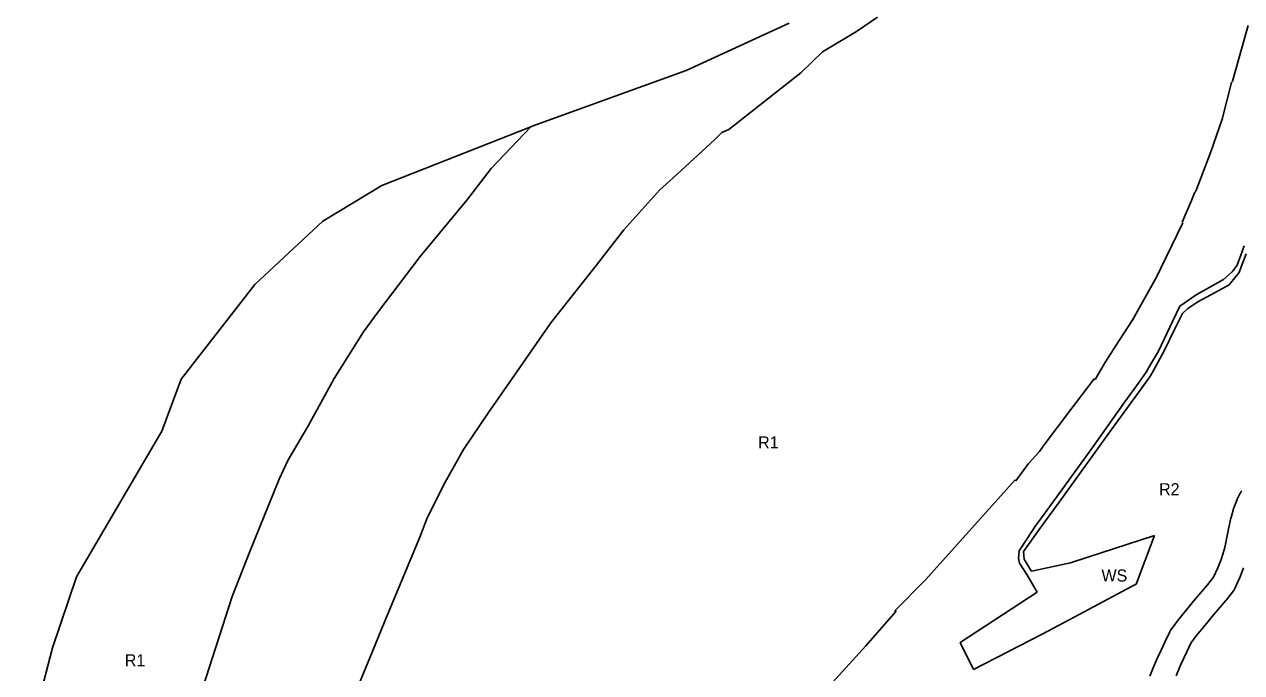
# Model space of a CAD drawing. Extents: x 7413438 to 7416393, y 5541665 to 5544118.
# Drawn here: x 7413443 to 7414051, y 5542525 to 5542849 of the extents above; entities that cross this region are included whole.
import ezdxf

# ---------------------------------------------------------------- set-up
doc = ezdxf.new("R2010")
doc.units = 0
doc.layers.add('linie_rozgraniczajace', color=7, linetype='Continuous')
doc.layers.add('oznaczenia_przeznaczen', color=7, linetype='Continuous')

msp = doc.modelspace()

# ---------------------------------------------------------------- linework, layer by layer
at = {"layer": 'linie_rozgraniczajace'}
for p, q in [((7413869.45, 5542852.48), (7413858.94, 5542845.23)), ((7413773.76, 5542825.75), (7413825.22, 5542849.45)), ((7413858.94, 5542845.23), (7413841.9, 5542835.15)), ((7414054.61, 5542848.19), (7414046.86, 5542820.34)), ((7413841.9, 5542835.15), (7413831.13, 5542824.66)), ((7413696.93, 5542797.92), (7413773.76, 5542825.75)), ((7413831.13, 5542824.66), (7413795.08, 5542796.31)), ((7414046.84, 5542820.33), (7414046.23, 5542819.81)), ((7414046.86, 5542820.34), (7414046.84, 5542820.33)), ((7414046.23, 5542819.81), (7414041.67, 5542801.46)), ((7413621.76, 5542768.27), (7413696.25, 5542797.65)), ((7413696.25, 5542797.65), (7413676.41, 5542776.84)), ((7413696.25, 5542797.65), (7413696.93, 5542797.92)), ((7413795.08, 5542796.31), (7413791.56, 5542794.75)), ((7414041.67, 5542801.46), (7414035.98, 5542785.07)), ((7413787.92, 5542791.04), (7413767.26, 5542772.18)), ((7413791.56, 5542794.75), (7413787.92, 5542791.04)), ((7414035.98, 5542785.07), (7414028.55, 5542765.43)), ((7413676.41, 5542776.84), (7413664.16, 5542760.89)), ((7413767.26, 5542772.18), (7413760.68, 5542766.04)), ((7413592.26, 5542750.42), (7413621.76, 5542768.27)), ((7413760.68, 5542766.04), (7413742.71, 5542746.15)), ((7414028.55, 5542765.43), (7414027.98, 5542764.93)), ((7413664.16, 5542760.89), (7413640.83, 5542732.82)), ((7414026.38, 5542760.85), (7414021.74, 5542749.9)), ((7414027.98, 5542764.93), (7414026.38, 5542760.85)), ((7413558.2, 5542718.88), (7413592.26, 5542750.42)), ((7414021.94, 5542749.71), (7414008.22, 5542721.17)), ((7414021.74, 5542749.9), (7414021.94, 5542749.71)), ((7413742.71, 5542746.15), (7413728.83, 5542728.33)), ((7414052.57, 5542738.17), (7414050.9, 5542733.49)), ((7413640.83, 5542732.82), (7413619.95, 5542705.13)), ((7414050.9, 5542733.49), (7414049.12, 5542728.52)), ((7414051.17, 5542727.63), (7414053.69, 5542734.12)), ((7413728.83, 5542728.33), (7413722.52, 5542720.3)), ((7414046.59, 5542725.22), (7414042.24, 5542721.37)), ((7414045.14, 5542718.61), (7414050.21, 5542724.83)), ((7414049.12, 5542728.52), (7414046.59, 5542725.22)), ((7414050.21, 5542724.83), (7414051.17, 5542727.63)), ((7413521.45, 5542671.43), (7413558.2, 5542718.88)), ((7413722.52, 5542720.3), (7413706.1, 5542699.62)), ((7414008.13, 5542721.26), (7413996.99, 5542701.33)), ((7414008.22, 5542721.17), (7414008.13, 5542721.26)), ((7414042.24, 5542721.37), (7414028.59, 5542713.58)), ((7414038.12, 5542714.82), (7414045.14, 5542718.61)), ((7414028.59, 5542713.58), (7414020.51, 5542707.94)), ((7414029.45, 5542710.14), (7414038.12, 5542714.82)), ((7413619.95, 5542705.13), (7413612.58, 5542695.16)), ((7414020.51, 5542707.94), (7414016.76, 5542700.29)), ((7414021.75, 5542704.28), (7414024.53, 5542706.88)), ((7414024.53, 5542706.88), (7414029.45, 5542710.14)), ((7413706.1, 5542699.62), (7413689.26, 5542675.23)), ((7413996.98, 5542701.34), (7413990.2, 5542690.75)), ((7413996.99, 5542701.33), (7413996.98, 5542701.34)), ((7414016.76, 5542700.29), (7414009.79, 5542685.54)), ((7414017.87, 5542696.28), (7414021.75, 5542704.28)), ((7413612.58, 5542695.16), (7413597.98, 5542671.81)), ((7414012.71, 5542685.63), (7414017.87, 5542696.28)), ((7413990.15, 5542690.76), (7413983.36, 5542680.23)), ((7413990.2, 5542690.75), (7413990.15, 5542690.76)), ((7413983.35, 5542680.23), (7413978.18, 5542671.36)), ((7413983.36, 5542680.23), (7413983.35, 5542680.23)), ((7414009.79, 5542685.54), (7414006.39, 5542679.6)), ((7414007.3, 5542675.86), (7414011.52, 5542683.49)), ((7414011.52, 5542683.49), (7414012.71, 5542685.63)), ((7413689.26, 5542675.23), (7413675.1, 5542654.93)), ((7414003.59, 5542675.01), (7414000.09, 5542670.09)), ((7414006.39, 5542679.6), (7414003.59, 5542675.01)), ((7414005.86, 5542673.25), (7414007.3, 5542675.86)), ((7413511.75, 5542645.52), (7413521.45, 5542671.43)), ((7413597.98, 5542671.81), (7413584.73, 5542647.85)), ((7413977.62, 5542671.62), (7413966.51, 5542657.01)), ((7413978.1, 5542671.39), (7413977.62, 5542671.62)), ((7413978.18, 5542671.36), (7413978.1, 5542671.39)), ((7414000.09, 5542670.09), (7413993.07, 5542660.22)), ((7413996.74, 5542660.53), (7414002.54, 5542668.48)), ((7414002.54, 5542668.48), (7414005.86, 5542673.25)), ((7413966.51, 5542657.01), (7413952.69, 5542638.7)), ((7413993.07, 5542660.22), (7413975.12, 5542635)), ((7413985.04, 5542644.49), (7413996.74, 5542660.53)), ((7413675.1, 5542654.93), (7413662.58, 5542636.31)), ((7413469.16, 5542572.7), (7413511.75, 5542645.52)), ((7413584.73, 5542647.85), (7413574.79, 5542630.94)), ((7413977.31, 5542633.81), (7413985.04, 5542644.49)), ((7413952.69, 5542638.7), (7413950.29, 5542635.4)), ((7413662.58, 5542636.31), (7413653.2, 5542619.62)), ((7413950.53, 5542635.53), (7413944.86, 5542629.38)), ((7413950.29, 5542635.4), (7413950.53, 5542635.53)), ((7413975.12, 5542635), (7413958.9, 5542612.62)), ((7413960.16, 5542610.09), (7413977.31, 5542633.81)), ((7413574.79, 5542630.94), (7413570.43, 5542621.47)), ((7413944.86, 5542629.38), (7413938.55, 5542620.67)), ((7413570.43, 5542621.47), (7413555.78, 5542585.31)), ((7413653.2, 5542619.62), (7413644.6, 5542602.58)), ((7413938.18, 5542621.18), (7413893.47, 5542571.16)), ((7413938.35, 5542620.94), (7413938.18, 5542621.18)), ((7413938.55, 5542620.67), (7413938.35, 5542620.94)), ((7414050.67, 5542614.52), (7414049.32, 5542611.82)), ((7414050.73, 5542614.63), (7414050.67, 5542614.52)), ((7414050.92, 5542614.98), (7414050.73, 5542614.63)), ((7414051.14, 5542615.3), (7414050.92, 5542614.98)), ((7414051.37, 5542615.62), (7414051.14, 5542615.3)), ((7414051.5, 5542615.77), (7414051.37, 5542615.62)), ((7413950.12, 5542596.36), (7413960.16, 5542610.09)), ((7413958.9, 5542612.62), (7413951.37, 5542602.21)), ((7414047.54, 5542607.27), (7414047.51, 5542607.18)), ((7414049.1, 5542611.31), (7414047.54, 5542607.27)), ((7414049.21, 5542611.58), (7414049.1, 5542611.31)), ((7414049.32, 5542611.82), (7414049.21, 5542611.58)), ((7413644.6, 5542602.58), (7413640.64, 5542592.55)), ((7413951.37, 5542602.21), (7413948.44, 5542598.18)), ((7414046.02, 5542602.04), (7414044.78, 5542596.7)), ((7414046.1, 5542602.35), (7414046.02, 5542602.04)), ((7414047.37, 5542606.77), (7414046.1, 5542602.35)), ((7414047.38, 5542606.81), (7414047.37, 5542606.77)), ((7414047.51, 5542607.18), (7414047.38, 5542606.81)), ((7413942.37, 5542585.38), (7413950.12, 5542596.36)), ((7413948.44, 5542598.18), (7413944.35, 5542591.98)), ((7414044.74, 5542596.51), (7414042.92, 5542587.35)), ((7414044.77, 5542596.66), (7414044.74, 5542596.51)), ((7414044.78, 5542596.7), (7414044.77, 5542596.66)), ((7413640.64, 5542592.55), (7413624.4, 5542553.49)), ((7413944.35, 5542591.98), (7413940.24, 5542585.74)), ((7414007.85, 5542593.32), (7413974.54, 5542582.57)), ((7413998.73, 5542569.12), (7414007.85, 5542593.32)), ((7413555.78, 5542585.31), (7413547.01, 5542562.96)), ((7413940.24, 5542585.74), (7413939.9, 5542581.99)), ((7413942.68, 5542581.49), (7413942.37, 5542585.38)), ((7414041.97, 5542584.06), (7414041.1, 5542581.34)), ((7414042.92, 5542587.35), (7414041.97, 5542584.06)), ((7413939.9, 5542581.99), (7413940.31, 5542579.55)), ((7413940.31, 5542579.55), (7413944.06, 5542573.97)), ((7413946.23, 5542575.65), (7413942.68, 5542581.49)), ((7413965.91, 5542579.78), (7413947.23, 5542575.74)), ((7413974.54, 5542582.57), (7413965.91, 5542579.78)), ((7414039.56, 5542577.25), (7414037.38, 5542572.54)), ((7414041.1, 5542581.34), (7414039.56, 5542577.25)), ((7414050.71, 5542572.81), (7414052.38, 5542577.25)), ((7413457.18, 5542537.24), (7413469.16, 5542572.7)), ((7413893.47, 5542571.16), (7413877.91, 5542555.51)), ((7413944.06, 5542573.97), (7413949.28, 5542565.04)), ((7413946.41, 5542575.56), (7413946.23, 5542575.65)), ((7413947.23, 5542575.74), (7413946.41, 5542575.56)), ((7414037.38, 5542572.54), (7414034.38, 5542568.7)), ((7414047.98, 5542566.88), (7414050.54, 5542572.41)), ((7414050.54, 5542572.41), (7414050.58, 5542572.5)), ((7414050.58, 5542572.5), (7414050.71, 5542572.81)), ((7413949.28, 5542565.04), (7413910.78, 5542539.98)), ((7413975.19, 5542556.61), (7413996.42, 5542567.89)), ((7413996.42, 5542567.89), (7413998.73, 5542569.12)), ((7414034.38, 5542568.7), (7414028.29, 5542561.68)), ((7414043.74, 5542561.19), (7414047.27, 5542565.7)), ((7414047.27, 5542565.7), (7414047.44, 5542565.94)), ((7414047.44, 5542565.94), (7414047.66, 5542566.27)), ((7414047.66, 5542566.27), (7414047.85, 5542566.61)), ((7414047.85, 5542566.61), (7414047.98, 5542566.88)), ((7413547.01, 5542562.96), (7413532.36, 5542517.51)), ((7414028.16, 5542561.54), (7414019.34, 5542550.69)), ((7414028.29, 5542561.68), (7414028.16, 5542561.54)), ((7414037.41, 5542553.89), (7414043.54, 5542560.95)), ((7414043.54, 5542560.95), (7414043.68, 5542561.11)), ((7414043.68, 5542561.11), (7414043.74, 5542561.19)), ((7413624.4, 5542553.49), (7413615.78, 5542532.27)), ((7413878.71, 5542555.53), (7413863.56, 5542538.17)), ((7413877.91, 5542555.51), (7413878.71, 5542555.53)), ((7413962.62, 5542549.92), (7413975.19, 5542556.61)), ((7414033.15, 5542548.66), (7414037.41, 5542553.89)), ((7413951.66, 5542544.1), (7413962.62, 5542549.92)), ((7414019.17, 5542550.48), (7414016.03, 5542546.25)), ((7414019.32, 5542550.67), (7414019.17, 5542550.48)), ((7414019.34, 5542550.69), (7414019.32, 5542550.67)), ((7414028.73, 5542543.22), (7414033.15, 5542548.66)), ((7413917.38, 5542526.36), (7413951.66, 5542544.1)), ((7414013.1, 5542540.36), (7414009.93, 5542533.61)), ((7414013.12, 5542540.4), (7414013.1, 5542540.36)), ((7414015.44, 5542545.26), (7414013.12, 5542540.4)), ((7414015.54, 5542545.46), (7414015.44, 5542545.26)), ((7414015.73, 5542545.8), (7414015.54, 5542545.46)), ((7414015.95, 5542546.13), (7414015.73, 5542545.8)), ((7414016.03, 5542546.25), (7414015.95, 5542546.13)), ((7414026.02, 5542539.57), (7414028.73, 5542543.22)), ((7413443.1, 5542482.71), (7413457.18, 5542537.24)), ((7413863.56, 5542538.17), (7413840.24, 5542512.6)), ((7413910.78, 5542539.98), (7413917.38, 5542526.36)), ((7414020.84, 5542528.61), (7414023.96, 5542535.25)), ((7414023.96, 5542535.25), (7414026.02, 5542539.57)), ((7413615.78, 5542532.27), (7413602.99, 5542501.5)), ((7414009.84, 5542533.42), (7414007.55, 5542528.03)), ((7414009.88, 5542533.5), (7414009.84, 5542533.42)), ((7414009.93, 5542533.61), (7414009.88, 5542533.5)), ((7414018.59, 5542523.33), (7414020.84, 5542528.61)), ((7414007.54, 5542528.01), (7414005.49, 5542523.16)), ((7414007.55, 5542528.03), (7414007.54, 5542528.01))]:
    msp.add_line(p, q, dxfattribs=at)

# ---------------------------------------------------------------- texts
at = {"layer": 'oznaczenia_przeznaczen'}
for s, p in [('R1', (7413809.76, 5542636.92)), ('R2', (7414010.12, 5542613.53)), ('WS', (7413981.32, 5542570.4)), ('R1', (7413493.28, 5542528.05))]:
    msp.add_text(s, height=6, dxfattribs=at).set_placement(p)

doc.saveas('drawing.dxf')
